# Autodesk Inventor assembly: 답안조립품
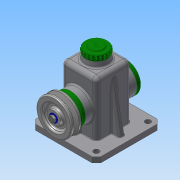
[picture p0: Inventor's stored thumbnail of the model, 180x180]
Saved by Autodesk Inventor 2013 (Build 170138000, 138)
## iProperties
Created: 2018-10
Part Number: 답안조립품
Document SubType Name: Assembly
Designer: Administrator
Author: Administrator
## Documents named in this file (14)
- C:\Users\Administrator\Desktop\481013V1010\답안조립품.iam
- C:\Users\Administrator\Desktop\481013V1010\본체.ipt
- C:\Users\Administrator\Desktop\481013V1010\V-벨트풀리.ipt
- C:\Users\Administrator\Desktop\481013V1010\뒤커버.ipt
- C:\Users\Administrator\Desktop\481013V1010\멈춤링 15 x 1.ipt
- C:\Users\Administrator\Desktop\481013V1010\베어링 15 x 35 x 11.ipt
- C:\Users\Administrator\Desktop\481013V1010\볼트 M4 x 10.ipt
- C:\Users\Administrator\Desktop\481013V1010\볼트 M6 x 12.ipt
- C:\Users\Administrator\Desktop\481013V1010\상부캡.ipt
- C:\Users\Administrator\Desktop\481013V1010\앞커버.ipt
- C:\Users\Administrator\Desktop\481013V1010\오일실 15 25 7.ipt
- C:\Users\Administrator\Desktop\481013V1010\와셔.ipt
- C:\Users\Administrator\Desktop\481013V1010\축.ipt
- C:\Users\Administrator\Desktop\481013V1010\키 5 x 5 x 14.ipt
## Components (1 placed, 1 different names)
1. V-벨트풀리:1
